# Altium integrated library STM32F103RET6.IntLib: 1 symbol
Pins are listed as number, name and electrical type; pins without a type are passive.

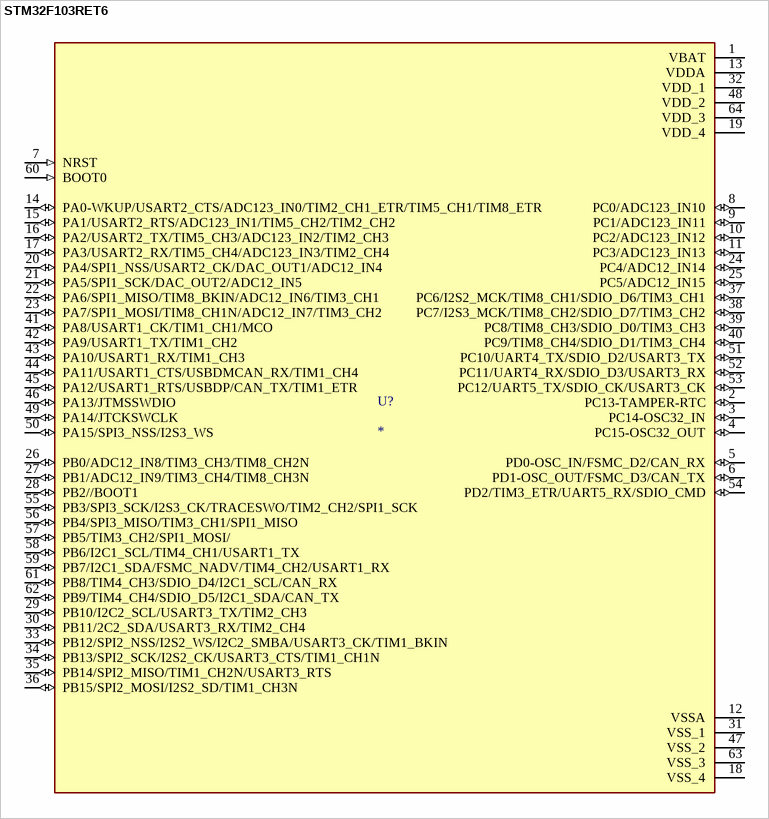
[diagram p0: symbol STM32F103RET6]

## STM32F103RET6
designator U?
ARMÂ® CortexÂ®-M3 STM32F1 Microcontroller IC 32-Bit 72MHz 512KB (512K x 8) FLASH 64-LQFP (10x10); MF: STMicroelectronics; MP: STM32F103RET6
footprint QFP50P1200X1200X160-64N
pins: 1 VBAT (power), 2 PC13-TAMPER-RTC (io), 3 PC14-OSC32_IN (io), 4 PC15-OSC32_OUT (io), 5 PD0-OSC_IN/FSMC_D2/CAN_RX (io), 6 PD1-OSC_OUT/FSMC_D3/CAN_TX (io), 7 NRST (in), 8 PC0/ADC123_IN10 (io), 9 PC1/ADC123_IN11 (io), 10 PC2/ADC123_IN12 (io), 11 PC3/ADC123_IN13 (io), 12 VSSA (power), 13 VDDA (power), 14 PA0-WKUP/USART2_CTS/ADC123_IN0/TIM2_CH1_ETR/TIM5_CH1/TIM8_ETR (io), 15 PA1/USART2_RTS/ADC123_IN1/TIM5_CH2/TIM2_CH2 (io), 16 PA2/USART2_TX/TIM5_CH3/ADC123_IN2/TIM2_CH3 (io), 17 PA3/USART2_RX/TIM5_CH4/ADC123_IN3/TIM2_CH4 (io), 18 VSS_4 (power), 19 VDD_4 (power), 20 PA4/SPI1_NSS/USART2_CK/DAC_OUT1/ADC12_IN4 (io), 21 PA5/SPI1_SCK/DAC_OUT2/ADC12_IN5 (io), 22 PA6/SPI1_MISO/TIM8_BKIN/ADC12_IN6/TIM3_CH1 (io), 23 PA7/SPI1_MOSI/TIM8_CH1N/ADC12_IN7/TIM3_CH2 (io), 24 PC4/ADC12_IN14 (io), 25 PC5/ADC12_IN15 (io), 26 PB0/ADC12_IN8/TIM3_CH3/TIM8_CH2N (io), 27 PB1/ADC12_IN9/TIM3_CH4/TIM8_CH3N (io), 28 PB2//BOOT1 (io), 29 PB10/I2C2_SCL/USART3_TX/TIM2_CH3 (io), 30 PB11/2C2_SDA/USART3_RX/TIM2_CH4 (io), 31 VSS_1 (power), 32 VDD_1 (power), 33 PB12/SPI2_NSS/I2S2_WS/I2C2_SMBA/USART3_CK/TIM1_BKIN (io), 34 PB13/SPI2_SCK/I2S2_CK/USART3_CTS/TIM1_CH1N (io), 35 PB14/SPI2_MISO/TIM1_CH2N/USART3_RTS (io), 36 PB15/SPI2_MOSI/I2S2_SD/TIM1_CH3N (io), 37 PC6/I2S2_MCK/TIM8_CH1/SDIO_D6/TIM3_CH1 (io), 38 PC7/I2S3_MCK/TIM8_CH2/SDIO_D7/TIM3_CH2 (io), 39 PC8/TIM8_CH3/SDIO_D0/TIM3_CH3 (io), 40 PC9/TIM8_CH4/SDIO_D1/TIM3_CH4 (io), 41 PA8/USART1_CK/TIM1_CH1/MCO (io), 42 PA9/USART1_TX/TIM1_CH2 (io), 43 PA10/USART1_RX/TIM1_CH3 (io), 44 PA11/USART1_CTS/USBDMCAN_RX/TIM1_CH4 (io), 45 PA12/USART1_RTS/USBDP/CAN_TX/TIM1_ETR (io), 46 PA13/JTMSSWDIO (io), 47 VSS_2 (power), 48 VDD_2 (power), 49 PA14/JTCKSWCLK (io), 50 PA15/SPI3_NSS/I2S3_WS (io), 51 PC10/UART4_TX/SDIO_D2/USART3_TX (io), 52 PC11/UART4_RX/SDIO_D3/USART3_RX (io), 53 PC12/UART5_TX/SDIO_CK/USART3_CK (io), 54 PD2/TIM3_ETR/UART5_RX/SDIO_CMD (io), 55 PB3/SPI3_SCK/I2S3_CK/TRACESWO/TIM2_CH2/SPI1_SCK (io), 56 PB4/SPI3_MISO/TIM3_CH1/SPI1_MISO (io), 57 PB5/TIM3_CH2/SPI1_MOSI/ (io), 58 PB6/I2C1_SCL/TIM4_CH1/USART1_TX (io), 59 PB7/I2C1_SDA/FSMC_NADV/TIM4_CH2/USART1_RX (io), 60 BOOT0 (in), 61 PB8/TIM4_CH3/SDIO_D4/I2C1_SCL/CAN_RX (io), 62 PB9/TIM4_CH4/SDIO_D5/I2C1_SDA/CAN_TX (io), 63 VSS_3 (power), 64 VDD_3 (power)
